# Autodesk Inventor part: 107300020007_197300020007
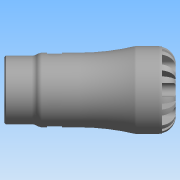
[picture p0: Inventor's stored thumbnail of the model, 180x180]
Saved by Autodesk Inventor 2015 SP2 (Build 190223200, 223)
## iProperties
Created: 2016-12
Part Number: 107300020007_197300020007
Material: Generic
Description: PLASSON FEMALE INTEGRAL BRASS THREAD 20X3/4" SERIES 1
Document SubType Name: Modeling
Designer: KIM
Density: 1 g/cm^3
Appearance: Default
Author: KIM
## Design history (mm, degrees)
derived "1073.ipt"
feature "Solid1::1073.ipt"
tag "TaggingFeature1"
body "Solid1"
other parameters: "d1" = 18.9, "d3" = 25, "d4" = 41, "d6" = 45, "d8" = 34.85, "d13" = 6.4, "d14" = 6.4, "d15" = 0, "d17" = 360 deg, "d19" = 8 deg, "d20" = 0.4, "d21" = 0.4, "d22" = 8 deg, "d24" = 0, "d26" = 360 deg, "d32" = 4.1, "d33" = 4.1, "d39" = 0.72351, "d42" = 24.117, "d43" = 31.98, "d46" = 1.66667, "d47" = 16, "d48" = 22.91115, "d50" = 6.27, "d51" = 0.41, "d54" = 7, "d55" = 4.4, "d57" = 12.544, "d58" = 0, "d68" = 360 deg, "d72" = 0.4, "d74" = 0, "d76" = 5.95, "E_" = 41, "l_" = 45, "G_" = 24.117, "l_2" = 16, "d9" = 8, "d11" = 41, "d12" = 25, "d49" = 19
